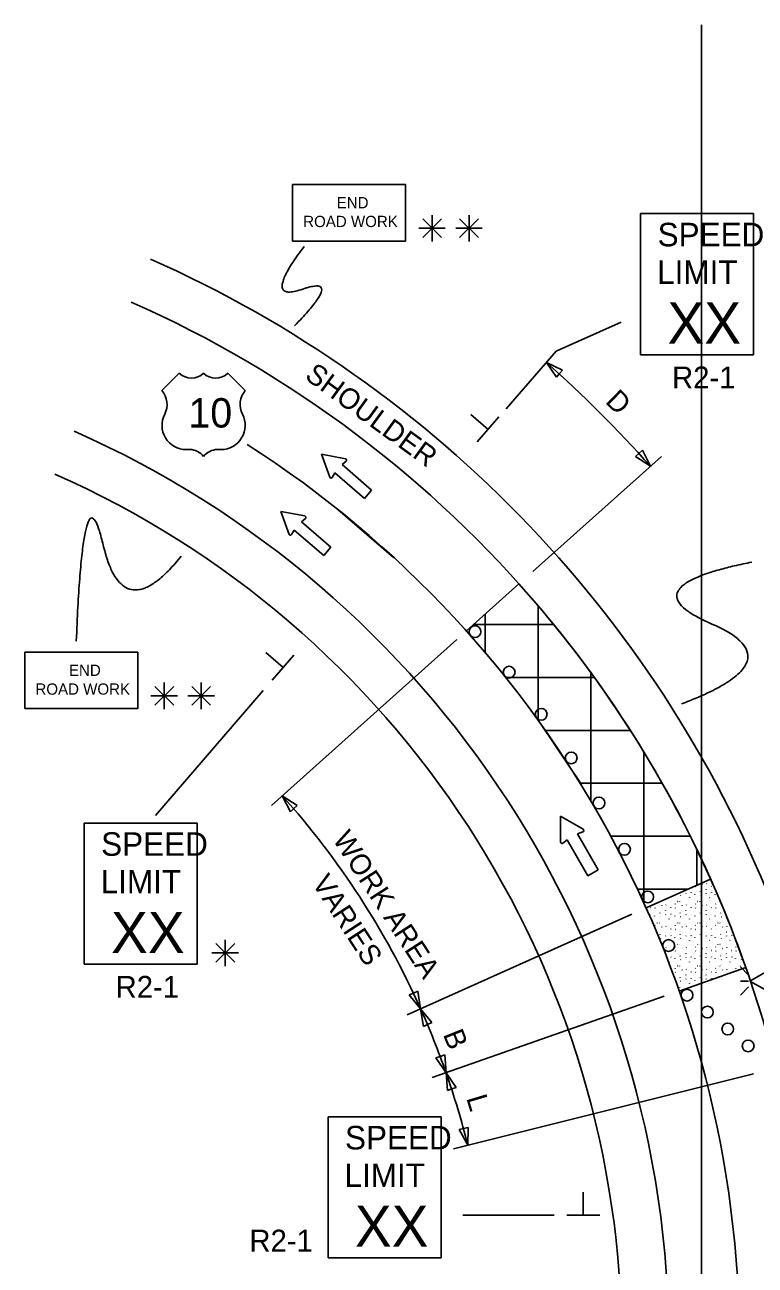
# Model space of a CAD drawing. Extents: x 16751 to 18479, y 5718 to 6974.
# Drawn here: x 16750.7 to 16999, y 6552.3 to 6974.1 of the extents above; entities that cross this region are included whole.
import ezdxf

# ---------------------------------------------------------------- set-up
doc = ezdxf.new("R2010")
doc.units = 0
for name, color, linetype in [('ALI_LEGAL_EX', 7, 'Continuous'), ('MT_SCRATCH_LEVEL_A', 7, 'Continuous'), ('MT_SCRATCH_LEVEL_E', 7, 'Continuous'), ('PAVT_EDGE_EX', 7, 'Continuous'), ('TRAFFIC_SIGNS_PR', 7, 'Continuous'), ('TYPICAL_EX', 7, 'Continuous'), ('TYPICAL_TEXT_DIMEN_PR', 7, 'Continuous')]:
    doc.layers.add(name, color=color, linetype=linetype)

msp = doc.modelspace()

# ---------------------------------------------------------------- linework, layer by layer
at = {"layer": 'ALI_LEGAL_EX'}
for p, q in [((16980.68, 6974.12), (16980.68, 6155.98)), ((16980.68, 6877.04), (16980.68, 6013.12))]:
    msp.add_line(p, q, dxfattribs=at)
for points in [[(16876.06, 6792.99), (16857.11, 6809.3)], [(16939.89, 6715.82), (16925.99, 6736.59)]]:
    msp.add_lwpolyline(points, dxfattribs=at)
msp.add_arc((16629.65, 6525.15), 364, 0, 57.2958, dxfattribs=at)
at = {"layer": 'MT_SCRATCH_LEVEL_A'}
for p, q in [((16918.68, 6784), (16900.8, 6767.99)), ((16918.68, 6784), (16900.8, 6767.99)), ((16925.15, 6737.43), (16925.15, 6776.33)), ((16903.28, 6770.2), (16930.27, 6770.2)), ((16907.15, 6760.43), (16907.15, 6773.68)), ((16943.15, 6709.93), (16943.15, 6753.45)), ((16914.07, 6752.2), (16944.07, 6752.2)), ((16927.54, 6734.2), (16956.3, 6734.2)), ((16961.15, 6675.37), (16961.15, 6726.68)), ((16939.35, 6716.2), (16967.15, 6716.2)), ((16949.72, 6698.2), (16976.74, 6698.2)), ((16979.15, 6681.58), (16979.15, 6693.23)), ((16983.8, 6683.65), (16961.89, 6673.85)), ((16961.89, 6673.85), (16983.8, 6683.65)), ((16983.8, 6683.65), (16961.89, 6673.85)), ((16980.98, 6681.91), (16981.03, 6681.84)), ((16982.43, 6682.06), (16982.48, 6682.18)), ((16984.05, 6681.24), (16984.1, 6681.16)), ((16958.82, 6680.2), (16976.08, 6680.2)), ((16969.7, 6677.27), (16969.74, 6677.37)), ((16973.63, 6678.11), (16973.69, 6678.03)), ((16975.41, 6678.78), (16975.47, 6678.89)), ((16976.59, 6677.27), (16976.64, 6677.39)), ((16977.21, 6679.03), (16977.26, 6678.95)), ((16978.49, 6678.45), (16978.5, 6678.33)), ((16978.69, 6681.1), (16978.74, 6681.02)), ((16980.33, 6679.31), (16980.38, 6679.42)), ((16980.52, 6678.11), (16980.57, 6678.03)), ((16982.26, 6680.18), (16982.31, 6680.1)), ((16982.3, 6678.78), (16982.35, 6678.89)), ((16983.48, 6677.27), (16983.53, 6677.39)), ((16984.1, 6679.03), (16984.15, 6678.95)), ((16985.38, 6678.45), (16985.39, 6678.33)), ((16963.39, 6673.95), (16963.44, 6673.87)), ((16964.84, 6675.08), (16964.89, 6675.19)), ((16964.92, 6673.81), (16964.97, 6673.73)), ((16967.21, 6674.63), (16967.26, 6674.55)), ((16968.48, 6672.89), (16968.53, 6672.81)), ((16968.65, 6674.78), (16968.71, 6674.9)), ((16970.27, 6673.95), (16970.33, 6673.87)), ((16971.72, 6675.08), (16971.78, 6675.19)), ((16971.8, 6673.81), (16971.85, 6673.73)), ((16972.49, 6676.04), (16972.54, 6675.96)), ((16973.22, 6676.01), (16973.28, 6675.93)), ((16974.09, 6674.63), (16974.15, 6674.55)), ((16975.37, 6672.89), (16975.42, 6672.81)), ((16975.54, 6674.78), (16975.59, 6674.9)), ((16977.16, 6673.95), (16977.21, 6673.87)), ((16978.61, 6675.08), (16978.66, 6675.19)), ((16978.69, 6673.81), (16978.74, 6673.73)), ((16979.38, 6676.04), (16979.43, 6675.96)), ((16980.11, 6676.01), (16980.16, 6675.93)), ((16980.98, 6674.63), (16981.03, 6674.55)), ((16982.26, 6672.89), (16982.31, 6672.81)), ((16982.43, 6674.78), (16982.48, 6674.9)), ((16984.05, 6673.95), (16984.1, 6673.87)), ((16985.5, 6675.08), (16985.55, 6675.19)), ((16985.58, 6673.81), (16985.63, 6673.73)), ((16986.26, 6676.04), (16986.31, 6675.96)), ((16987, 6676.01), (16987.05, 6675.93)), ((16963.44, 6671.74), (16963.49, 6671.66)), ((16964.72, 6671.17), (16964.73, 6671.05)), ((16965.6, 6668.75), (16965.65, 6668.68)), ((16966.34, 6668.72), (16966.39, 6668.65)), ((16966.56, 6672.02), (16966.61, 6672.14)), ((16966.75, 6670.82), (16966.8, 6670.74)), ((16968.53, 6671.49), (16968.58, 6671.61)), ((16969.7, 6669.99), (16969.76, 6670.11)), ((16970.32, 6671.74), (16970.37, 6671.66)), ((16971.6, 6671.17), (16971.62, 6671.05)), ((16972.49, 6668.75), (16972.54, 6668.68)), ((16973.22, 6668.72), (16973.28, 6668.65)), ((16973.44, 6672.02), (16973.5, 6672.14)), ((16973.63, 6670.82), (16973.69, 6670.74)), ((16975.41, 6671.49), (16975.47, 6671.61)), ((16976.59, 6669.99), (16976.64, 6670.11)), ((16977.21, 6671.74), (16977.26, 6671.66)), ((16978.49, 6671.17), (16978.5, 6671.05)), ((16979.38, 6668.75), (16979.43, 6668.68)), ((16980.11, 6668.72), (16980.16, 6668.65)), ((16980.33, 6672.02), (16980.38, 6672.14)), ((16980.52, 6670.82), (16980.57, 6670.74)), ((16982.3, 6671.49), (16982.35, 6671.61)), ((16983.48, 6669.99), (16983.53, 6670.11)), ((16984.1, 6671.74), (16984.15, 6671.66)), ((16985.38, 6671.17), (16985.39, 6671.05)), ((16986.26, 6668.75), (16986.31, 6668.68)), ((16987, 6668.72), (16987.05, 6668.65)), ((16987.22, 6672.02), (16987.27, 6672.14)), ((16987.41, 6670.82), (16987.46, 6670.74)), ((16964.84, 6667.79), (16964.89, 6667.91)), ((16966.56, 6664.74), (16966.61, 6664.85)), ((16967.21, 6667.34), (16967.26, 6667.27)), ((16968.48, 6665.61), (16968.53, 6665.53)), ((16968.53, 6664.21), (16968.58, 6664.32)), ((16968.65, 6667.49), (16968.71, 6667.61)), ((16970.27, 6666.67), (16970.33, 6666.59)), ((16970.32, 6664.46), (16970.37, 6664.38)), ((16971.72, 6667.79), (16971.78, 6667.91)), ((16971.8, 6666.53), (16971.85, 6666.45)), ((16973.44, 6664.74), (16973.5, 6664.85)), ((16974.09, 6667.34), (16974.15, 6667.27)), ((16975.37, 6665.61), (16975.42, 6665.53)), ((16975.41, 6664.21), (16975.47, 6664.32)), ((16975.54, 6667.49), (16975.59, 6667.61)), ((16977.16, 6666.67), (16977.21, 6666.59)), ((16977.21, 6664.46), (16977.26, 6664.38)), ((16978.61, 6667.79), (16978.66, 6667.91)), ((16978.69, 6666.53), (16978.74, 6666.45)), ((16980.33, 6664.74), (16980.38, 6664.85)), ((16980.98, 6667.34), (16981.03, 6667.27)), ((16982.26, 6665.61), (16982.31, 6665.53)), ((16982.3, 6664.21), (16982.35, 6664.32)), ((16982.43, 6667.49), (16982.48, 6667.61)), ((16984.05, 6666.67), (16984.1, 6666.59)), ((16984.1, 6664.46), (16984.15, 6664.38)), ((16985.5, 6667.79), (16985.55, 6667.91)), ((16985.58, 6666.53), (16985.63, 6666.45)), ((16987.22, 6664.74), (16987.27, 6664.85)), ((16987.87, 6667.34), (16987.92, 6667.27)), ((16989.15, 6665.61), (16989.2, 6665.53)), ((16989.19, 6664.21), (16989.24, 6664.32)), ((16989.32, 6667.49), (16989.37, 6667.61)), ((16990.99, 6664.46), (16991.04, 6664.38)), ((16966.75, 6663.54), (16966.8, 6663.46)), ((16968.65, 6660.21), (16968.71, 6660.33)), ((16969.7, 6662.7), (16969.76, 6662.82)), ((16971.6, 6663.88), (16971.62, 6663.76)), ((16971.72, 6660.51), (16971.78, 6660.62)), ((16972.49, 6661.47), (16972.54, 6661.39)), ((16973.22, 6661.44), (16973.28, 6661.36)), ((16973.63, 6663.54), (16973.69, 6663.46)), ((16974.09, 6660.06), (16974.15, 6659.98)), ((16975.54, 6660.21), (16975.59, 6660.33)), ((16976.59, 6662.7), (16976.64, 6662.82)), ((16978.49, 6663.88), (16978.5, 6663.76)), ((16978.61, 6660.51), (16978.66, 6660.62)), ((16979.38, 6661.47), (16979.43, 6661.39)), ((16980.11, 6661.44), (16980.16, 6661.36)), ((16980.52, 6663.54), (16980.57, 6663.46)), ((16980.98, 6660.06), (16981.03, 6659.98)), ((16982.43, 6660.21), (16982.48, 6660.33)), ((16983.48, 6662.7), (16983.53, 6662.82)), ((16985.38, 6663.88), (16985.39, 6663.76)), ((16985.5, 6660.51), (16985.55, 6660.62)), ((16986.26, 6661.47), (16986.31, 6661.39)), ((16987, 6661.44), (16987.05, 6661.36)), ((16987.41, 6663.54), (16987.46, 6663.46)), ((16987.87, 6660.06), (16987.92, 6659.98)), ((16989.32, 6660.21), (16989.37, 6660.33)), ((16990.37, 6662.7), (16990.42, 6662.82)), ((16992.39, 6660.51), (16992.44, 6660.62)), ((16968.48, 6658.32), (16968.53, 6658.24)), ((16970.27, 6659.38), (16970.33, 6659.3)), ((16970.32, 6657.17), (16970.37, 6657.09)), ((16971.6, 6656.6), (16971.62, 6656.48)), ((16971.8, 6659.24), (16971.85, 6659.16)), ((16973.44, 6657.45), (16973.5, 6657.57)), ((16973.63, 6656.25), (16973.69, 6656.18)), ((16975.37, 6658.32), (16975.42, 6658.24)), ((16975.41, 6656.92), (16975.47, 6657.04)), ((16977.16, 6659.38), (16977.21, 6659.3)), ((16977.21, 6657.17), (16977.26, 6657.09)), ((16978.49, 6656.6), (16978.5, 6656.48)), ((16978.69, 6659.24), (16978.74, 6659.16)), ((16980.33, 6657.45), (16980.38, 6657.57)), ((16980.52, 6656.25), (16980.57, 6656.18)), ((16982.26, 6658.32), (16982.31, 6658.24)), ((16982.3, 6656.92), (16982.35, 6657.04)), ((16984.05, 6659.38), (16984.1, 6659.3)), ((16984.1, 6657.17), (16984.15, 6657.09)), ((16985.38, 6656.6), (16985.39, 6656.48)), ((16985.58, 6659.24), (16985.63, 6659.16)), ((16987.22, 6657.45), (16987.27, 6657.57)), ((16987.41, 6656.25), (16987.46, 6656.18)), ((16989.15, 6658.32), (16989.2, 6658.24)), ((16989.19, 6656.92), (16989.24, 6657.04)), ((16990.94, 6659.38), (16990.99, 6659.3)), ((16990.99, 6657.17), (16991.04, 6657.09)), ((16992.27, 6656.6), (16992.28, 6656.48)), ((16992.47, 6659.24), (16992.52, 6659.16)), ((16994.11, 6657.45), (16994.16, 6657.57)), ((16994.3, 6656.25), (16994.35, 6656.18)), ((16969.7, 6655.42), (16969.76, 6655.54)), ((16971.72, 6653.22), (16971.78, 6653.34)), ((16971.8, 6651.96), (16971.85, 6651.88)), ((16972.49, 6654.18), (16972.54, 6654.11)), ((16995.8, 6653.51), (16973.15, 6645.57)), ((16973.15, 6645.57), (16995.8, 6653.51)), ((16973.22, 6654.15), (16973.28, 6654.07)), ((16974.09, 6652.77), (16974.15, 6652.7)), ((16975.54, 6652.93), (16975.59, 6653.04)), ((16976.59, 6655.42), (16976.64, 6655.54)), ((16977.16, 6652.1), (16977.21, 6652.02)), ((16978.61, 6653.22), (16978.66, 6653.34)), ((16978.69, 6651.96), (16978.74, 6651.88)), ((16979.38, 6654.18), (16979.43, 6654.11)), ((16980.11, 6654.15), (16980.16, 6654.07)), ((16980.98, 6652.77), (16981.03, 6652.7)), ((16982.43, 6652.93), (16982.48, 6653.04)), ((16983.48, 6655.42), (16983.53, 6655.54)), ((16984.05, 6652.1), (16984.1, 6652.02)), ((16985.5, 6653.22), (16985.55, 6653.34)), ((16985.58, 6651.96), (16985.63, 6651.88)), ((16986.26, 6654.18), (16986.31, 6654.11)), ((16987, 6654.15), (16987.05, 6654.07)), ((16987.87, 6652.77), (16987.92, 6652.7)), ((16989.32, 6652.93), (16989.37, 6653.04)), ((16990.37, 6655.42), (16990.42, 6655.54)), ((16990.94, 6652.1), (16990.99, 6652.02)), ((16992.39, 6653.22), (16992.44, 6653.34)), ((16993.15, 6654.18), (16993.2, 6654.11)), ((16993.89, 6654.15), (16993.94, 6654.07)), ((16973.44, 6650.17), (16973.5, 6650.28)), ((16973.63, 6648.97), (16973.69, 6648.89)), ((16975.37, 6651.04), (16975.42, 6650.96)), ((16975.41, 6649.64), (16975.47, 6649.75)), ((16976.59, 6648.13), (16976.64, 6648.25)), ((16977.21, 6649.89), (16977.26, 6649.81)), ((16978.49, 6649.31), (16978.5, 6649.19)), ((16980.33, 6650.17), (16980.38, 6650.28)), ((16980.52, 6648.97), (16980.57, 6648.89)), ((16982.26, 6651.04), (16982.31, 6650.96)), ((16982.3, 6649.64), (16982.35, 6649.75)), ((16984.1, 6649.89), (16984.15, 6649.81)), ((16973.22, 6646.87), (16973.28, 6646.79))]:
    msp.add_line(p, q, dxfattribs=at)
for start, end in [(24.1122, 41.8471), (19.3199, 24.1122)]:
    msp.add_arc((16629.65, 6525.15), 388, start, end, dxfattribs=at)
at = {"layer": 'MT_SCRATCH_LEVEL_E'}
for p, q in [((16859.73, 6826.53), (16851.54, 6828.11)), ((16851.54, 6828.11), (16854.35, 6820.27)), ((16858.54, 6824.58), (16859.94, 6825.72)), ((16868.59, 6815.93), (16858.54, 6824.58)), ((16855.18, 6820.19), (16856.1, 6821.74)), ((16856.1, 6821.74), (16866.15, 6813.1)), ((16866.15, 6813.1), (16868.59, 6815.93)), ((16845.92, 6807.1), (16837.72, 6808.67)), ((16837.72, 6808.67), (16840.53, 6800.84)), ((16844.72, 6805.15), (16846.12, 6806.29)), ((16854.77, 6796.5), (16844.72, 6805.15)), ((16841.36, 6800.76), (16842.28, 6802.31)), ((16842.28, 6802.31), (16852.33, 6793.66)), ((16852.33, 6793.66), (16854.77, 6796.5))]:
    msp.add_line(p, q, dxfattribs=at)
for centre, start, end in [((16859.64, 6826.07), 309.3361, 79.073), ((16854.78, 6820.43), 199.7248, 329.2637), ((16845.82, 6806.64), 309.3361, 79.073), ((16840.97, 6801), 199.7248, 329.2637)]:
    msp.add_arc(centre, 0.463, start, end, dxfattribs=at)
at = {"layer": 'PAVT_EDGE_EX'}
for radius, start in [(404, 21.0961), (388, 14.0482), (340, 0), (324, 0)]:
    msp.add_arc((16629.65, 6525.15), radius, start, 66.0906, dxfattribs=at)
at = {"layer": 'TRAFFIC_SIGNS_PR'}
for p, q in [((16960.03, 6909.92), (16998.43, 6909.92)), ((16960.03, 6861.92), (16960.03, 6909.92)), ((16998.43, 6861.92), (16998.43, 6909.92)), ((16960.03, 6861.92), (16998.43, 6861.92)), ((16770.9, 6702.69), (16809.3, 6702.69)), ((16770.9, 6654.69), (16770.9, 6702.69)), ((16809.3, 6654.69), (16809.3, 6702.69)), ((16770.9, 6654.69), (16809.3, 6654.69)), ((16993.92, 6653.82), (16996.74, 6651.01)), ((16996.74, 6648.97), (16993.92, 6648.97)), ((16993.92, 6644.12), (16996.74, 6646.94)), ((16853.78, 6602.83), (16892.18, 6602.83)), ((16853.78, 6554.83), (16853.78, 6602.83)), ((16892.18, 6554.83), (16892.18, 6602.83)), ((16853.78, 6554.83), (16892.18, 6554.83))]:
    msp.add_line(p, q, dxfattribs=at)
for points in [[(16841.72, 6900.59), (16880.12, 6900.59), (16880.12, 6919.79), (16841.72, 6919.79)], [(16750.71, 6741.59), (16789.11, 6741.59), (16789.11, 6760.79), (16750.71, 6760.79)]]:
    msp.add_lwpolyline(points, close=True, dxfattribs=at)
msp.add_lwpolyline([(17002.5, 6651.99), (16997.19, 6648.97), (17002.5, 6645.93)], dxfattribs=at)
for centre in [(16903.73, 6767.76), (16915.33, 6753.99), (16926.23, 6739.67), (16936.42, 6724.84), (16945.86, 6709.51), (16954.54, 6693.75), (16962.44, 6677.57), (16969.53, 6661.03), (16975.8, 6644.16), (16982.72, 6638.4), (16989.65, 6632.65), (16996.57, 6626.9)]:
    msp.add_circle(centre, 2, dxfattribs=at)
at = {"layer": 'TYPICAL_EX'}
for p, q in [((16797.33, 6849.74), (16803.22, 6855.64)), ((16825.62, 6849.74), (16819.73, 6855.64)), ((16805.57, 6829.68), (16806.75, 6829.68)), ((16817.38, 6829.68), (16816.2, 6829.68))]:
    msp.add_line(p, q, dxfattribs=at)
for centre, radius, start, end in [((16807.35, 6859.93), 5.96, 226.1404, 313.8596), ((16815.6, 6859.93), 5.96, 226.1404, 313.8596), ((16791.74, 6845.02), 7.31, 333.0977, 40.1936), ((16831.21, 6845.02), 7.31, 139.8064, 206.9023), ((16805.58, 6837.93), 8.24, 152.6698, 269.9013), ((16817.36, 6837.93), 8.24, 270.0987, 27.3302), ((16806.76, 6823.78), 5.91, 37.1038, 90.1385), ((16816.18, 6823.78), 5.91, 89.8615, 142.8962)]:
    msp.add_arc(centre, radius, start, end, dxfattribs=at)
at = {"layer": 'TYPICAL_TEXT_DIMEN_PR'}
for p, q in [((16889.14, 6904.97), (16889.14, 6909.42)), ((16901.7, 6904.97), (16901.7, 6909.42)), ((16889.14, 6904.97), (16884.61, 6904.97)), ((16885.96, 6908.15), (16892.33, 6901.78)), ((16892.33, 6908.15), (16885.96, 6901.78)), ((16889.14, 6904.97), (16892.33, 6904.97)), ((16889.14, 6904.97), (16893.62, 6904.97)), ((16889.14, 6904.97), (16889.14, 6900.47)), ((16901.7, 6904.97), (16897.17, 6904.97)), ((16898.51, 6908.15), (16904.89, 6901.78)), ((16904.89, 6908.15), (16898.51, 6901.78)), ((16901.7, 6904.97), (16904.89, 6904.97)), ((16901.7, 6904.97), (16906.18, 6904.97)), ((16901.7, 6904.97), (16901.7, 6900.47)), ((16931.32, 6863.17), (16953.37, 6873.01)), ((16931.32, 6863.17), (16914.34, 6843.48)), ((16931.42, 6854.32), (16928.01, 6859.34)), ((16928.01, 6859.34), (16933.48, 6856.7)), ((16932.45, 6855.51), (16931.42, 6854.32)), ((16933.48, 6856.7), (16932.45, 6855.51)), ((16908.16, 6836.56), (16902.26, 6841.65)), ((16911.83, 6840.82), (16904.48, 6832.31)), ((16959.47, 6828.39), (16960.64, 6829.44)), ((16960.64, 6829.44), (16963.38, 6824.03)), ((16967.1, 6827.36), (16923.44, 6788.26)), ((16958.3, 6827.35), (16959.47, 6828.39)), ((16963.38, 6824.03), (16958.3, 6827.35)), ((16897.57, 6765.1), (16834.51, 6708.61)), ((16838.5, 6755.55), (16832.6, 6760.63)), ((16842.17, 6759.8), (16834.82, 6751.29)), ((16794.95, 6749.15), (16801.32, 6742.78)), ((16801.32, 6749.15), (16794.95, 6742.78)), ((16798.13, 6745.96), (16798.13, 6750.42)), ((16807.5, 6749.15), (16813.88, 6742.78)), ((16813.88, 6749.15), (16807.5, 6742.78)), ((16810.69, 6745.96), (16810.69, 6750.42)), ((16798.13, 6745.96), (16793.6, 6745.96)), ((16831.74, 6747.71), (16795.08, 6705.2)), ((16798.13, 6745.96), (16801.32, 6745.96)), ((16798.13, 6745.96), (16802.61, 6745.96)), ((16798.13, 6745.96), (16798.13, 6741.46)), ((16810.69, 6745.96), (16806.16, 6745.96)), ((16810.69, 6745.96), (16813.88, 6745.96)), ((16810.69, 6745.96), (16815.17, 6745.96)), ((16810.69, 6745.96), (16810.69, 6741.46)), ((16840.97, 6706.53), (16838.23, 6711.95)), ((16838.23, 6711.95), (16843.31, 6708.63)), ((16842.14, 6707.58), (16840.97, 6706.53)), ((16843.31, 6708.63), (16842.14, 6707.58)), ((16940.45, 6700.55), (16932.78, 6705.06)), ((16932.78, 6705.06), (16932.81, 6696.18)), ((16938.56, 6699.01), (16940.37, 6699.66)), ((16945.58, 6686.74), (16938.56, 6699.01)), ((16933.61, 6695.8), (16935.09, 6697.03)), ((16935.09, 6697.03), (16942.12, 6684.76)), ((16942.12, 6684.76), (16945.58, 6686.74)), ((16957.06, 6671.69), (16880.65, 6637.49)), ((16815.67, 6661.73), (16822.05, 6655.35)), ((16822.05, 6661.73), (16815.67, 6655.35)), ((16818.86, 6658.54), (16818.86, 6662.99)), ((16818.86, 6658.54), (16814.33, 6658.54)), ((16818.86, 6658.54), (16822.05, 6658.54)), ((16818.86, 6658.54), (16823.34, 6658.54)), ((16818.86, 6658.54), (16818.86, 6654.04)), ((16881.39, 6644.24), (16882.82, 6644.88)), ((16885.22, 6639.53), (16881.39, 6644.24)), ((16882.82, 6644.88), (16884.26, 6645.53)), ((16884.26, 6645.53), (16885.22, 6639.53)), ((16968.07, 6643.79), (16889.16, 6616.13)), ((16886.18, 6633.54), (16885.22, 6639.53)), ((16885.22, 6639.53), (16889.05, 6634.82)), ((16889.05, 6634.82), (16887.61, 6634.18)), ((16887.61, 6634.18), (16886.18, 6633.54)), ((16890.46, 6622.79), (16891.94, 6623.31)), ((16893.88, 6617.78), (16890.46, 6622.79)), ((16891.94, 6623.31), (16893.42, 6623.83)), ((16893.42, 6623.83), (16893.88, 6617.78)), ((16894.34, 6611.73), (16893.88, 6617.78)), ((16893.88, 6617.78), (16897.3, 6612.77)), ((16998.34, 6617.4), (16896.42, 6591.9)), ((16895.82, 6612.25), (16894.34, 6611.73)), ((16897.3, 6612.77), (16895.82, 6612.25)), ((16898.33, 6598.42), (16899.85, 6598.8)), ((16901.28, 6593.11), (16898.33, 6598.42)), ((16899.85, 6598.8), (16901.38, 6599.18)), ((16901.38, 6599.18), (16901.28, 6593.11)), ((16940.52, 6569.33), (16940.52, 6577.11)), ((16930.65, 6569.33), (16899.56, 6569.33)), ((16934.9, 6569.33), (16946.15, 6569.33))]:
    msp.add_line(p, q, dxfattribs=at)
for centre, radius, start, end in [((16629.65, 6525.15), 448, 41.8471, 48.2417), ((16629.65, 6525.15), 280, 24.1124, 41.8469), ((16940.19, 6700.13), 0.494, 289.8203, 59.5572), ((16933.3, 6696.18), 0.494, 180.2089, 309.7479), ((16629.65, 6525.15), 280, 19.32, 24.1124), ((16629.65, 6525.15), 280, 14.0482, 19.32)]:
    msp.add_arc(centre, radius, start, end, dxfattribs=at)
for points in [[(16842.4, 6871.8), (16859.35, 6889.13), (16830.95, 6879.33), (16845.63, 6898.7)], [(16803.88, 6793.44), (16784.01, 6768.65), (16770.64, 6825.95), (16768.21, 6764.58)], [(16997.83, 6791.4), (16955.03, 6782.98), (17013.14, 6757.9), (16973.96, 6743.21)]]:
    msp.add_open_spline(points, degree=2, dxfattribs=at)

# ---------------------------------------------------------------- texts
at = {"layer": 'TRAFFIC_SIGNS_PR'}
for s, height, p in [('END', 3.831, (16856.72, 6911.72)), ('ROAD WORK', 3.831, (16845.33, 6905.34)), ('SPEED', 8, (16965.8, 6898.79)), ('LIMIT', 8, (16965.64, 6885.99)), ('XX', 14.031, (16969.15, 6865.68)), ('R2-1', 7.44, (16970.71, 6850.48)), ('END', 3.831, (16765.71, 6752.72)), ('ROAD WORK', 3.831, (16754.32, 6746.33)), ('SPEED', 8, (16776.66, 6691.55)), ('LIMIT', 8, (16776.5, 6678.75)), ('XX', 14.031, (16780.01, 6658.44)), ('R2-1', 7.44, (16781.57, 6643.25)), ('SPEED', 8, (16859.54, 6591.7)), ('LIMIT', 8, (16859.38, 6578.9)), ('XX', 14.031, (16862.89, 6558.59)), ('R2-1', 7.44, (16827.05, 6556.97))]:
    msp.add_text(s, height=height, dxfattribs=at).set_placement(p)
at = {"layer": 'TYPICAL_EX'}
msp.add_text('10', height=10, dxfattribs=at).set_placement((16806.32, 6837.17))
at = {"layer": 'TYPICAL_TEXT_DIMEN_PR'}
for s, rotation, p in [('SHOULDER', 323.9582, (16845.52, 6853.96)), ('D', 315.5356, (16947.69, 6845.74)), ('WORK AREA', 302.9795, (16855.13, 6697.17)), ('VARIES', 302.9795, (16848.09, 6682.3)), ('B', 291.7155, (16892.75, 6630.86)), ('L', 286.685, (16900.73, 6609.19))]:
    msp.add_text(s, height=7, rotation=rotation, dxfattribs=at).set_placement(p)

doc.saveas('drawing.dxf')
